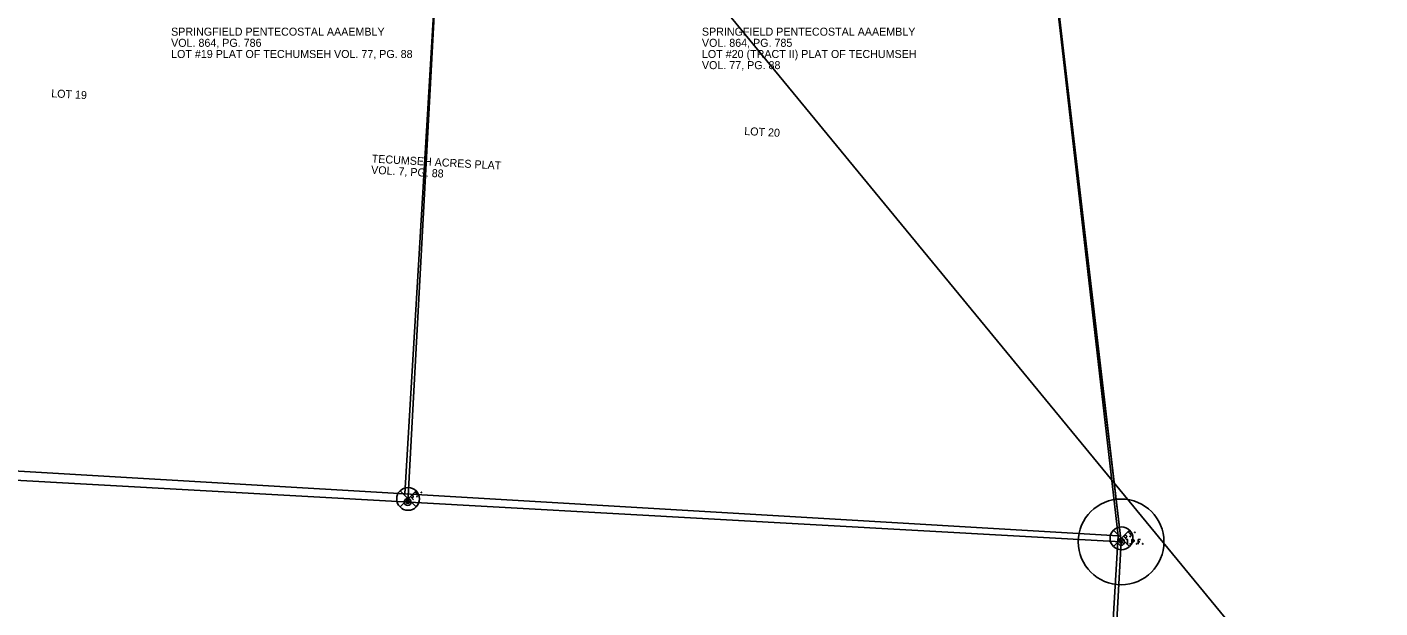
# Model space of a CAD drawing. Extents: x 1532954 to 1577849, y 698998 to 706606.
# Drawn here: x 1572033.3 to 1572506.6, y 702582.2 to 702785.4 of the extents above; entities that cross this region are included whole.
import ezdxf

# ---------------------------------------------------------------- set-up
doc = ezdxf.new("R2010")
doc.units = 0
for name, color, linetype in [('Default', 7, 'Continuous'), ('DV_X_Lot_Line', 7, 'Continuous'), ('DV_X_Property_Line', 7, 'Continuous'), ('RW_X_Text', 7, 'Continuous'), ('SC_Scratch1', 7, 'Continuous'), ('SC_Scratch2', 7, 'Continuous'), ('SC_Scratch3', 7, 'Continuous'), ('SC_Scratch4', 7, 'Continuous'), ('SC_Scratch9', 7, 'Continuous'), ('SV_X_Mon_Cells_Found', 7, 'Continuous')]:
    doc.layers.add(name, color=color, linetype=linetype)

msp = doc.modelspace()

# ---------------------------------------------------------------- linework, layer by layer
at = {"layer": 'Default'}
for p, q in [((1572163.79, 702623.15), (1572169.45, 702617.49)), ((1572163.79, 702617.49), (1572169.45, 702623.15)), ((1572166.62, 702620.32), (1572166.62, 702620.32)), ((1572413.41, 702609.33), (1572419.06, 702603.67)), ((1572413.41, 702603.67), (1572419.06, 702609.33)), ((1572416.23, 702606.5), (1572416.23, 702606.5))]:
    msp.add_line(p, q, dxfattribs=at)
for centre in [(1572166.62, 702620.32), (1572416.23, 702606.5)]:
    msp.add_circle(centre, 4, dxfattribs=at)
at = {"layer": 'DV_X_Lot_Line'}
for p, q in [((1572166.48, 702619.22), (1572182.89, 702920.2)), ((1571916.87, 702633.17), (1572416.09, 702605.27))]:
    msp.add_line(p, q, dxfattribs=at)
at = {"layer": 'DV_X_Property_Line'}
for q in [(1572375.54, 702946.46), (1572310.03, 700708.23), (1572410.5, 702505.42)]:
    msp.add_line((1572416.09, 702605.27), q, dxfattribs=at)
at = {"layer": 'SC_Scratch1'}
msp.add_lwpolyline([(1572365.62, 701708.75), (1572371.48, 701808.58), (1572376.97, 701902.02), (1572377.3, 701908.41), (1572382.44, 702008.28), (1572387.57, 702108.15), (1572392.71, 702208.02), (1572397.85, 702307.89), (1572401.43, 702377.55), (1572403.22, 702407.75), (1572409.15, 702507.57), (1572415.08, 702607.4), (1572380.43, 702909.4), (1572375.87, 702949.15), (1572687.31, 702991.85), (1572800.34, 703007.35), (1572915.11, 703023.08), (1572964.59, 703029.87), (1572962.2, 702989.16), (1572818.71, 700543.9)], dxfattribs=at)
for points in [[(1572380.43, 702909.4), (1572415.08, 702607.4), (1572165.51, 702622.06), (1572180.96, 702882.05), (1572183.37, 702922.76), (1572200.89, 702925.16), (1572375.87, 702949.15)], [(1572165.51, 702622.06), (1571940.9, 702635.26), (1571915.94, 702636.73), (1571918.93, 702687.02), (1571930.88, 702888.14), (1572183.37, 702922.76), (1572180.96, 702882.05)], [(1571940.9, 702635.26), (1572165.51, 702622.06), (1572415.08, 702607.4), (1572409.15, 702507.57), (1571934.97, 702535.44), (1571910.01, 702536.9), (1571914.28, 702608.67), (1571915.94, 702636.73)]]:
    msp.add_lwpolyline(points, close=True, dxfattribs=at)
at = {"layer": 'SC_Scratch2'}
msp.add_line((1573640.53, 701135.41), (1571969.28, 703165.9), dxfattribs=at)
at = {"layer": 'SC_Scratch3'}
for p, q in [((1572375.46, 702947.16), (1572416.09, 702605.27)), ((1572166.48, 702619.22), (1572182.93, 702921)), ((1571916.87, 702633.17), (1572416.09, 702605.27)), ((1572315.61, 700808.07), (1572416.09, 702605.27))]:
    msp.add_line(p, q, dxfattribs=at)
for points in [[(1572168.5, 702619.96), (1572167.43, 702621.15), (1572167.82, 702621.5), (1572167.87, 702621.53), (1572167.95, 702621.56), (1572167.99, 702621.57), (1572168.03, 702621.57), (1572168.1, 702621.55), (1572168.17, 702621.53), (1572168.25, 702621.47), (1572168.35, 702621.35), (1572168.38, 702621.31), (1572168.41, 702621.24), (1572168.44, 702621.14), (1572168.43, 702621.09), (1572168.43, 702621.04), (1572168.4, 702620.99), (1572168.34, 702620.92), (1572167.95, 702620.57)], [(1572169.67, 702623.16), (1572169.1, 702622.65), (1572170.17, 702621.46)], [(1572169.58, 702621.21), (1572169.62, 702621.25), (1572169.66, 702621.25), (1572169.72, 702621.24), (1572169.76, 702621.19), (1572169.77, 702621.13), (1572169.76, 702621.09), (1572169.72, 702621.05), (1572169.68, 702621.05), (1572169.62, 702621.07), (1572169.58, 702621.11), (1572169.57, 702621.17), (1572169.58, 702621.21)], [(1572169.62, 702622.07), (1572170.03, 702622.43)], [(1572171.18, 702622.65), (1572171.22, 702622.69), (1572171.26, 702622.69), (1572171.32, 702622.67), (1572171.36, 702622.63), (1572171.37, 702622.57), (1572171.36, 702622.53), (1572171.32, 702622.49), (1572171.28, 702622.49), (1572171.22, 702622.5), (1572171.18, 702622.55), (1572171.17, 702622.61), (1572171.18, 702622.65)], [(1572418.11, 702606), (1572417.04, 702607.19), (1572417.43, 702607.55), (1572417.48, 702607.58), (1572417.56, 702607.61), (1572417.6, 702607.61), (1572417.64, 702607.61), (1572417.71, 702607.6), (1572417.78, 702607.57), (1572417.86, 702607.51), (1572417.97, 702607.4), (1572417.99, 702607.35), (1572418.02, 702607.28), (1572418.05, 702607.19), (1572418.04, 702607.13), (1572418.04, 702607.09), (1572418.01, 702607.03), (1572417.95, 702606.97), (1572417.56, 702606.61)], [(1572419.28, 702609.2), (1572418.71, 702608.7), (1572419.78, 702607.5)], [(1572419.19, 702607.26), (1572419.23, 702607.3), (1572419.27, 702607.3), (1572419.33, 702607.28), (1572419.37, 702607.24), (1572419.38, 702607.18), (1572419.37, 702607.14), (1572419.33, 702607.1), (1572419.29, 702607.1), (1572419.23, 702607.11), (1572419.19, 702607.16), (1572419.18, 702607.22), (1572419.19, 702607.26)], [(1572419.23, 702608.11), (1572419.64, 702608.47)], [(1572420.79, 702608.69), (1572420.83, 702608.73), (1572420.87, 702608.73), (1572420.93, 702608.72), (1572420.97, 702608.67), (1572420.98, 702608.61), (1572420.97, 702608.57), (1572420.93, 702608.53), (1572420.89, 702608.53), (1572420.83, 702608.55), (1572420.79, 702608.59), (1572420.78, 702608.65), (1572420.79, 702608.69)]]:
    msp.add_lwpolyline(points, dxfattribs=at)
for centre, radius in [((1572166.48, 702619.22), 1.2), ((1572166.48, 702619.22), 0.495), ((1572416.09, 702605.27), 1.2), ((1572416.09, 702605.27), 0.495)]:
    msp.add_circle(centre, radius, dxfattribs=at)
at = {"layer": 'SC_Scratch4'}
for p, q in [((1572375.91, 702947.21), (1572416.09, 702605.27)), ((1572416.09, 702605.27), (1572315.61, 700808.07))]:
    msp.add_line(p, q, dxfattribs=at)
for points in [[(1572418.11, 702606), (1572417.04, 702607.19), (1572417.43, 702607.55), (1572417.48, 702607.58), (1572417.56, 702607.61), (1572417.6, 702607.61), (1572417.64, 702607.61), (1572417.71, 702607.6), (1572417.78, 702607.57), (1572417.86, 702607.51), (1572417.97, 702607.4), (1572417.99, 702607.35), (1572418.02, 702607.28), (1572418.05, 702607.19), (1572418.04, 702607.13), (1572418.04, 702607.09), (1572418.01, 702607.03), (1572417.95, 702606.97), (1572417.56, 702606.61)], [(1572419.28, 702609.2), (1572418.71, 702608.7), (1572419.78, 702607.5)], [(1572419.19, 702607.26), (1572419.23, 702607.3), (1572419.27, 702607.3), (1572419.33, 702607.28), (1572419.37, 702607.24), (1572419.38, 702607.18), (1572419.37, 702607.14), (1572419.33, 702607.1), (1572419.29, 702607.1), (1572419.23, 702607.11), (1572419.19, 702607.16), (1572419.18, 702607.22), (1572419.19, 702607.26)], [(1572419.23, 702608.11), (1572419.64, 702608.47)], [(1572420.79, 702608.69), (1572420.83, 702608.73), (1572420.87, 702608.73), (1572420.93, 702608.72), (1572420.97, 702608.67), (1572420.98, 702608.61), (1572420.97, 702608.57), (1572420.93, 702608.53), (1572420.89, 702608.53), (1572420.83, 702608.55), (1572420.79, 702608.59), (1572420.78, 702608.65), (1572420.79, 702608.69)]]:
    msp.add_lwpolyline(points, dxfattribs=at)
for radius in [1.2, 0.495]:
    msp.add_circle((1572416.09, 702605.27), radius, dxfattribs=at)
at = {"layer": 'SC_Scratch9'}
msp.add_circle((1572416.09, 702605.27), 15, dxfattribs=at)
at = {"layer": 'SV_X_Mon_Cells_Found'}
for points in [[(1572418.1, 702606.07), (1572418.45, 702606.07)], [(1572418.28, 702604.47), (1572418.28, 702606.07)], [(1572419.84, 702604.47), (1572419.84, 702606.07), (1572420.37, 702606.07), (1572420.43, 702606.05), (1572420.5, 702606.03), (1572420.54, 702606), (1572420.57, 702605.98), (1572420.61, 702605.91), (1572420.65, 702605.85), (1572420.67, 702605.75), (1572420.67, 702605.6), (1572420.66, 702605.55), (1572420.64, 702605.47), (1572420.59, 702605.39), (1572420.55, 702605.35), (1572420.51, 702605.32), (1572420.46, 702605.3), (1572420.37, 702605.28), (1572419.84, 702605.28)], [(1572422.85, 702606.07), (1572422.09, 702606.07), (1572422.09, 702604.47)], [(1572418.1, 702604.47), (1572418.45, 702604.47)], [(1572419.24, 702604.68), (1572419.29, 702604.68), (1572419.32, 702604.65), (1572419.36, 702604.6), (1572419.36, 702604.54), (1572419.32, 702604.49), (1572419.29, 702604.47), (1572419.24, 702604.47), (1572419.2, 702604.49), (1572419.17, 702604.54), (1572419.17, 702604.6), (1572419.2, 702604.65), (1572419.24, 702604.68)], [(1572421.48, 702604.68), (1572421.54, 702604.68), (1572421.57, 702604.65), (1572421.61, 702604.6), (1572421.61, 702604.54), (1572421.57, 702604.49), (1572421.54, 702604.47), (1572421.48, 702604.47), (1572421.45, 702604.49), (1572421.42, 702604.54), (1572421.42, 702604.6), (1572421.45, 702604.65), (1572421.48, 702604.68)], [(1572422.09, 702605.28), (1572422.63, 702605.28)], [(1572423.63, 702604.68), (1572423.69, 702604.68), (1572423.72, 702604.65), (1572423.75, 702604.6), (1572423.75, 702604.54), (1572423.72, 702604.49), (1572423.69, 702604.47), (1572423.63, 702604.47), (1572423.6, 702604.49), (1572423.57, 702604.54), (1572423.57, 702604.6), (1572423.6, 702604.65), (1572423.63, 702604.68)]]:
    msp.add_lwpolyline(points, dxfattribs=at)
msp.add_circle((1572416.09, 702605.27), 1.2, dxfattribs=at)

# ---------------------------------------------------------------- texts
at = {"layer": 'RW_X_Text'}
for s, p in [('VOL. 864, PG. 786', (1572083.7, 702778.53)), ('SPRINGFIELD PENTECOSTAL AAAEMBLY', (1572083.7, 702782.43)), ('VOL. 864, PG. 785', (1572269.42, 702778.53)), ('SPRINGFIELD PENTECOSTAL AAAEMBLY', (1572269.42, 702782.43)), ('LOT #19 PLAT OF TECHUMSEH VOL. 77, PG. 88', (1572083.7, 702774.62)), ('LOT #20 (TRACT II) PLAT OF TECHUMSEH', (1572269.42, 702774.62)), ('VOL. 77, PG. 88', (1572269.42, 702770.72))]:
    msp.add_text(s, height=2.8, dxfattribs=at).set_placement(p)
at = {"layer": 'SC_Scratch3'}
for s, p in [('LOT 19', (1572041.7, 702760.89)), ('LOT 20', (1572284.18, 702747.69)), ('TECUMSEH ACRES PLAT', (1572153.84, 702738.03)), ('VOL. 7, PG. 88', (1572153.63, 702734.13))]:
    msp.add_text(s, height=2.8, rotation=356.8835, dxfattribs=at).set_placement(p)

doc.saveas('drawing.dxf')
